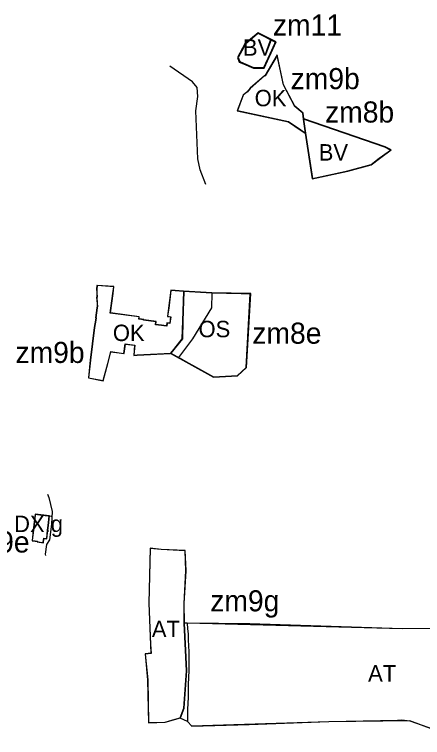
# Model space of a CAD drawing. Extents: x -555070 to -553076, y -1186731 to -1182766.
# Drawn here: x -554417 to -554069, y -1184951 to -1184334 of the extents above; entities that cross this region are included whole.
import ezdxf

# ---------------------------------------------------------------- set-up
doc = ezdxf.new("R2010")
doc.units = 0
for name, color, linetype in [('HRANICE_ZMENY_DO_KOO', 7, 'Continuous'), ('Level 10', 7, 'Continuous'), ('Level 13', 7, 'Continuous'), ('Level 52', 7, 'Continuous'), ('Level 59', 7, 'Continuous'), ('Level 6', 7, 'Continuous'), ('MISTNI_KOMUNIKACE_stav', 7, 'Continuous'), ('OBRYS_PLOCH', 7, 'Continuous'), ('stav_AT', 7, 'Continuous'), ('stav_BV', 7, 'Continuous'), ('stav_DS', 7, 'Continuous'), ('stav_DXg', 7, 'Continuous'), ('stav_OK', 7, 'Continuous'), ('stav_OS', 7, 'Continuous'), ('ZU_plocha_aktualizace', 7, 'Continuous')]:
    doc.layers.add(name, color=color, linetype=linetype)

msp = doc.modelspace()

# ---------------------------------------------------------------- linework, layer by layer
at = {"layer": 'HRANICE_ZMENY_DO_KOO'}
msp.add_line((-554170.7, -1184423.54), (-554169.02, -1184435.57), dxfattribs=at)
for points in [[(-554204.25, -1184380.05), (-554194.19, -1184357.79), (-554209.52, -1184350.02), (-554220.67, -1184359.48), (-554226.98, -1184370.98), (-554225.47, -1184374.96), (-554221.96, -1184376.43), (-554213.49, -1184380), (-554211.97, -1184380.01)], [(-554399.94, -1184765.08), (-554400.17, -1184767.15), (-554400.44, -1184769.55), (-554400.93, -1184774.02), (-554401.95, -1184783.16), (-554399.44, -1184783.43), (-554397.51, -1184783.67), (-554397.57, -1184784.17), (-554392.25, -1184784.89), (-554391.85, -1184781.28), (-554389.33, -1184781.56), (-554388.51, -1184774.24), (-554388.05, -1184770.15), (-554387.22, -1184761.92), (-554399.42, -1184760.41)], [(-554301.44, -1184789.58), (-554302.64, -1184836.28), (-554300.72, -1184879.16), (-554305.71, -1184879.61), (-554303.67, -1184901.89), (-554302.85, -1184938.39), (-554288.7, -1184937.94), (-554275.67, -1184934.24), (-554272.55, -1184925.87), (-554270.19, -1184894.22), (-554272.24, -1184853.44), (-554272.28, -1184836.55), (-554270.85, -1184808.75), (-554271.5, -1184791.46), (-554292.05, -1184790.49)]]:
    msp.add_lwpolyline(points, close=True, dxfattribs=at)
for points in [[(-554170.53, -1184423.3), (-554171.2, -1184418.47), (-554178.03, -1184412.62), (-554187.72, -1184394.38), (-554193.22, -1184368.87), (-554203.65, -1184386.6), (-554203.99, -1184386.56), (-554216.26, -1184397.25), (-554218.76, -1184400.42), (-554219.11, -1184400.51), (-554222.23, -1184403.12), (-554227.38, -1184416.4), (-554183.67, -1184425.84), (-554173.56, -1184432.74), (-554172.15, -1184433.69), (-554169.35, -1184435.59)], [(-554169.32, -1184435.56), (-554169.32, -1184435.61), (-554163.45, -1184474.47), (-554132.96, -1184468.04), (-554113.03, -1184462.64), (-554106.06, -1184457.1), (-554096.22, -1184449.91), (-554101.32, -1184447.27), (-554170.49, -1184423.29)], [(-554273.04, -1184570.31), (-554283.81, -1184569.6), (-554285.81, -1184584.81), (-554286.74, -1184591.94), (-554284.08, -1184592.29), (-554284.75, -1184597.62), (-554287.08, -1184597.32), (-554287.42, -1184599.95), (-554289.84, -1184599.65), (-554291.82, -1184599.4), (-554296.54, -1184598.82), (-554296.2, -1184596.16), (-554306.74, -1184594.81), (-554306.7, -1184594.51), (-554308.7, -1184594.25), (-554310.86, -1184593.98), (-554310.63, -1184592.16), (-554335.2, -1184588.84), (-554332.98, -1184572.3), (-554332.19, -1184566.38), (-554346.75, -1184565.41), (-554346.94, -1184568.7), (-554346.86, -1184571.43), (-554346.75, -1184575.32), (-554347.06, -1184575.34), (-554346.6, -1184580.77), (-554346.54, -1184583.06), (-554346.72, -1184584.4), (-554347.88, -1184593.15), (-554347.58, -1184593.18), (-554347.84, -1184595.11), (-554349.06, -1184601.17), (-554352.43, -1184629.22), (-554354, -1184644.34), (-554341.37, -1184646.71), (-554337.36, -1184632.03), (-554334.77, -1184622.09), (-554327.87, -1184623.02), (-554323.62, -1184623.6), (-554322.51, -1184615.46), (-554314.58, -1184616.47), (-554315.42, -1184625.1), (-554312.31, -1184624.93), (-554284.35, -1184623.41), (-554284.24, -1184623.27)], [(-554284.26, -1184623.26), (-554247.54, -1184643.65), (-554226.85, -1184642.64), (-554219.22, -1184635.44), (-554215.77, -1184572.36), (-554248.91, -1184571.82), (-554273.04, -1184570.31)], [(-554283.34, -1184622.57), (-554273.98, -1184610.94), (-554273.55, -1184595.75), (-554272.83, -1184570.65)], [(-554272.24, -1184853.24), (-554269.87, -1184853.21), (-554086.74, -1184858.06), (-553988.58, -1184857.13), (-553905.89, -1184852.24), (-553902.54, -1184904.97), (-553896.32, -1184936.49), (-553914.33, -1184946.76), (-553944.12, -1184950.99), (-554005.65, -1184950.01), (-554060.25, -1184944.18), (-554080.26, -1184936.83), (-554149.14, -1184937.65), (-554266, -1184941.39), (-554269.56, -1184937.38), (-554275.75, -1184934.43)]]:
    msp.add_lwpolyline(points, dxfattribs=at)
at = {"layer": 'Level 13'}
for p, q in [((-554210.23, -1184351.28), (-554220.28, -1184359.8)), ((-554209.45, -1184350.62), (-554210.23, -1184351.28)), ((-554194.84, -1184358.02), (-554209.45, -1184350.62)), ((-554220.28, -1184359.8), (-554226.43, -1184371.02)), ((-554199.26, -1184367.81), (-554195.27, -1184358.97)), ((-554195.27, -1184358.97), (-554194.84, -1184358.02)), ((-554226.43, -1184371.02), (-554225.08, -1184374.58)), ((-554204.57, -1184379.55), (-554199.26, -1184367.81)), ((-554225.08, -1184374.58), (-554221.77, -1184375.97)), ((-554221.77, -1184375.97), (-554213.39, -1184379.5)), ((-554213.39, -1184379.5), (-554211.97, -1184379.51)), ((-554211.97, -1184379.51), (-554206.78, -1184379.54)), ((-554206.78, -1184379.54), (-554206.13, -1184379.54)), ((-554206.13, -1184379.54), (-554204.57, -1184379.55)), ((-554170.7, -1184423.54), (-554169.02, -1184435.57)), ((-554101.44, -1184447.55), (-554170.7, -1184423.54)), ((-554169.02, -1184435.57), (-554163.2, -1184474.11)), ((-554106.24, -1184456.86), (-554096.79, -1184449.95)), ((-554096.79, -1184449.95), (-554101.44, -1184447.55)), ((-554163.2, -1184474.11), (-554133.03, -1184467.75)), ((-554248.93, -1184572.12), (-554272.74, -1184570.53)), ((-554223.99, -1184572.53), (-554248.93, -1184572.12)), ((-554216.08, -1184572.66), (-554223.99, -1184572.53)), ((-554223.99, -1184572.53), (-554223.99, -1184572.53)), ((-554283.78, -1184623.18), (-554277.24, -1184626.81)), ((-554277.24, -1184626.81), (-554271.13, -1184630.21)), ((-554271.13, -1184630.21), (-554247.47, -1184643.35)), ((-554247.47, -1184643.35), (-554226.98, -1184642.35))]:
    msp.add_line(p, q, dxfattribs=at)
for points in [[(-554133.03, -1184467.75), (-554113.17, -1184462.37), (-554106.24, -1184456.86)], [(-554272.74, -1184570.53), (-554273.46, -1184595.6), (-554273.9, -1184610.9), (-554283.78, -1184623.18)], [(-554226.98, -1184642.35), (-554219.51, -1184635.3), (-554216.08, -1184572.66)], [(-554223.99, -1184572.53), (-554223.99, -1184572.53)]]:
    msp.add_lwpolyline(points, dxfattribs=at)
at = {"layer": 'Level 52'}
for points in [[(-554163.2, -1184474.11), (-554133.03, -1184467.75), (-554113.17, -1184462.37), (-554106.24, -1184456.86), (-554096.79, -1184449.95)], [(-554275.96, -1184627.52), (-554271.13, -1184630.21), (-554247.47, -1184643.35), (-554226.98, -1184642.35), (-554219.51, -1184635.3), (-554216.08, -1184572.66)]]:
    msp.add_lwpolyline(points, dxfattribs=at)
at = {"layer": 'Level 6'}
msp.add_lwpolyline([(-554254.04, -1184479.36), (-554258.7, -1184466.92), (-554260.67, -1184457.41), (-554262.38, -1184416.47), (-554260.91, -1184404.26), (-554261.32, -1184396.65), (-554265.33, -1184391.9), (-554284.73, -1184378.38)], dxfattribs=at)
at = {"layer": 'MISTNI_KOMUNIKACE_stav'}
msp.add_lwpolyline([(-554388.84, -1184743.39), (-554387.7, -1184746.36), (-554384.96, -1184758.32), (-554385.53, -1184769.11), (-554387.14, -1184782.39), (-554389.79, -1184786.41), (-554390.89, -1184794.71), (-554390.5, -1184795.62)], dxfattribs=at)
at = {"layer": 'OBRYS_PLOCH'}
for p, q in [((-554210.23, -1184351.28), (-554220.28, -1184359.8)), ((-554209.45, -1184350.62), (-554210.23, -1184351.28)), ((-554194.84, -1184358.02), (-554209.45, -1184350.62)), ((-554220.28, -1184359.8), (-554226.43, -1184371.02)), ((-554199.26, -1184367.81), (-554195.27, -1184358.97)), ((-554195.27, -1184358.97), (-554194.84, -1184358.02)), ((-554226.43, -1184371.02), (-554225.08, -1184374.58)), ((-554204.57, -1184379.55), (-554199.26, -1184367.81)), ((-554193.31, -1184369.41), (-554203.54, -1184386.81)), ((-554225.08, -1184374.58), (-554221.77, -1184375.97)), ((-554221.77, -1184375.97), (-554213.39, -1184379.5)), ((-554213.39, -1184379.5), (-554211.97, -1184379.51)), ((-554211.97, -1184379.51), (-554206.78, -1184379.54)), ((-554206.78, -1184379.54), (-554206.13, -1184379.54)), ((-554206.13, -1184379.54), (-554204.57, -1184379.55)), ((-554171.39, -1184418.57), (-554178.19, -1184412.75)), ((-554227.11, -1184416.25), (-554183.59, -1184425.65)), ((-554170.7, -1184423.54), (-554171.39, -1184418.57)), ((-554183.59, -1184425.65), (-554173.45, -1184432.57)), ((-554170.7, -1184423.54), (-554169.02, -1184435.57)), ((-554101.44, -1184447.55), (-554170.7, -1184423.54)), ((-554169.02, -1184435.57), (-554170.7, -1184423.54)), ((-554173.45, -1184432.57), (-554172.04, -1184433.52)), ((-554172.04, -1184433.52), (-554169.02, -1184435.57)), ((-554169.02, -1184435.57), (-554163.2, -1184474.11)), ((-554106.24, -1184456.86), (-554096.79, -1184449.95)), ((-554096.79, -1184449.95), (-554101.44, -1184447.55)), ((-554163.2, -1184474.11), (-554133.03, -1184467.75)), ((-554248.93, -1184572.12), (-554272.74, -1184570.53)), ((-554223.99, -1184572.53), (-554248.93, -1184572.12)), ((-554216.08, -1184572.66), (-554223.99, -1184572.53)), ((-554223.99, -1184572.53), (-554223.99, -1184572.53)), ((-554283.78, -1184623.18), (-554247.47, -1184643.35)), ((-554283.78, -1184623.18), (-554277.24, -1184626.81)), ((-554277.24, -1184626.81), (-554271.13, -1184630.21)), ((-554271.13, -1184630.21), (-554247.47, -1184643.35)), ((-554247.47, -1184643.35), (-554226.98, -1184642.35)), ((-554399.24, -1184760.63), (-554399.74, -1184765.1)), ((-554393.26, -1184761.37), (-554399.24, -1184760.63)), ((-554399.74, -1184765.1), (-554399.97, -1184767.17)), ((-554387.44, -1184762.09), (-554393.26, -1184761.37)), ((-554388.25, -1184770.13), (-554387.44, -1184762.09)), ((-554400.24, -1184769.57), (-554400.73, -1184774.04)), ((-554399.97, -1184767.17), (-554400.24, -1184769.57)), ((-554401.23, -1184778.51), (-554401.73, -1184782.98)), ((-554400.73, -1184774.04), (-554401.23, -1184778.51)), ((-554401.73, -1184782.98), (-554399.42, -1184783.23)), ((-554399.42, -1184783.23), (-554397.29, -1184783.5)), ((-554397.29, -1184783.5), (-554397.35, -1184784)), ((-554397.35, -1184784), (-554392.43, -1184784.66)), ((-554392.43, -1184784.66), (-554392.03, -1184781.06)), ((-554392.03, -1184781.06), (-554389.51, -1184781.34)), ((-554301.25, -1184789.8), (-554302.44, -1184836.28)), ((-554292.06, -1184790.69), (-554301.25, -1184789.8)), ((-554271.69, -1184791.65), (-554292.06, -1184790.69)), ((-554271.05, -1184808.75), (-554271.69, -1184791.65)), ((-554302.44, -1184836.28), (-554301.22, -1184871.51)), ((-554270.39, -1184894.22), (-554272.44, -1184853.45)), ((-554216.47, -1184853.91), (-554269.87, -1184853.41)), ((-554269.87, -1184853.41), (-554269.56, -1184858.15)), ((-554086.74, -1184858.26), (-554216.47, -1184853.91)), ((-553988.57, -1184857.33), (-554086.74, -1184858.26)), ((-554301.22, -1184871.51), (-554300.51, -1184879.34)), ((-554300.51, -1184879.34), (-554305.49, -1184879.79)), ((-554305.49, -1184879.79), (-554303.47, -1184901.88)), ((-554303.47, -1184901.88), (-554302.65, -1184938.18)), ((-554302.65, -1184938.18), (-554288.73, -1184937.74)), ((-554288.73, -1184937.74), (-554279.99, -1184935.26))]:
    msp.add_line(p, q, dxfattribs=at)
for points in [[(-554178.19, -1184412.75), (-554187.91, -1184394.45), (-554193.31, -1184369.41)], [(-554203.54, -1184386.81), (-554203.92, -1184386.77), (-554216.11, -1184397.39), (-554218.65, -1184400.6), (-554219.02, -1184400.69), (-554222.06, -1184403.24), (-554227.11, -1184416.25)], [(-554133.03, -1184467.75), (-554113.17, -1184462.37), (-554106.24, -1184456.86)], [(-554272.74, -1184570.53), (-554273.46, -1184595.6), (-554273.9, -1184610.9), (-554283.78, -1184623.18)], [(-554226.98, -1184642.35), (-554219.51, -1184635.3), (-554216.08, -1184572.66)], [(-554223.99, -1184572.53), (-554223.99, -1184572.53)], [(-554389.51, -1184781.34), (-554388.71, -1184774.22), (-554388.25, -1184770.13)], [(-554272.44, -1184853.45), (-554272.48, -1184836.55), (-554271.05, -1184808.75)], [(-554269.56, -1184858.15), (-554269.11, -1184862.54), (-554269.07, -1184863.55), (-554268.92, -1184867.71), (-554268.65, -1184872.8), (-554268.39, -1184877.88), (-554268.44, -1184885.89), (-554268.51, -1184889.87), (-554268.58, -1184893.83), (-554268.93, -1184905.83), (-554269.02, -1184911.25), (-554269.11, -1184916.67), (-554269.51, -1184927.1), (-554269.45, -1184933.6), (-554269.44, -1184937.22)], [(-554279.99, -1184935.26), (-554275.82, -1184934.08), (-554272.75, -1184925.83), (-554270.39, -1184894.22)], [(-554269.44, -1184937.22), (-554265.91, -1184941.19), (-554217.06, -1184939.95), (-554149.14, -1184937.45)], [(-554149.14, -1184937.45), (-554090.76, -1184936.24), (-554087.05, -1184935.87), (-554080.23, -1184936.63), (-554060.2, -1184943.98)]]:
    msp.add_lwpolyline(points, dxfattribs=at)
msp.add_lwpolyline([(-554341.51, -1184646.48), (-554337.55, -1184631.98), (-554334.92, -1184621.87), (-554327.84, -1184622.82), (-554323.79, -1184623.37), (-554322.68, -1184615.23), (-554314.36, -1184616.3), (-554315.2, -1184624.89), (-554312.32, -1184624.73), (-554283.78, -1184623.18), (-554273.9, -1184610.9), (-554273.46, -1184595.6), (-554272.74, -1184570.53), (-554283.64, -1184569.81), (-554285.61, -1184584.84), (-554286.52, -1184591.77), (-554283.86, -1184592.12), (-554284.58, -1184597.84), (-554286.91, -1184597.54), (-554287.25, -1184600.17), (-554289.86, -1184599.85), (-554291.84, -1184599.6), (-554296.76, -1184598.99), (-554296.42, -1184596.33), (-554306.96, -1184594.98), (-554306.92, -1184594.68), (-554308.73, -1184594.45), (-554311.09, -1184594.15), (-554310.85, -1184592.33), (-554335.42, -1184589.01), (-554333.18, -1184572.27), (-554332.42, -1184566.56), (-554346.56, -1184565.62), (-554346.74, -1184568.7), (-554346.66, -1184571.42), (-554346.54, -1184575.51), (-554346.84, -1184575.53), (-554346.4, -1184580.76), (-554346.34, -1184583.07), (-554346.52, -1184584.43), (-554347.65, -1184592.97), (-554347.35, -1184593), (-554347.64, -1184595.14), (-554348.86, -1184601.2), (-554352.23, -1184629.24), (-554353.78, -1184644.18)], close=True, dxfattribs=at)
at = {"layer": 'stav_AT'}
for p, q in [((-554301.25, -1184789.8), (-554302.44, -1184836.28)), ((-554292.06, -1184790.69), (-554301.25, -1184789.8)), ((-554271.69, -1184791.65), (-554292.06, -1184790.69)), ((-554271.05, -1184808.75), (-554271.69, -1184791.65)), ((-554302.44, -1184836.28), (-554301.22, -1184871.51)), ((-554270.39, -1184894.22), (-554272.44, -1184853.45)), ((-554216.47, -1184853.91), (-554269.87, -1184853.41)), ((-554269.87, -1184853.41), (-554269.56, -1184858.15)), ((-554086.74, -1184858.26), (-554216.47, -1184853.91)), ((-553988.57, -1184857.33), (-554086.74, -1184858.26)), ((-554301.22, -1184871.51), (-554300.51, -1184879.34)), ((-554300.51, -1184879.34), (-554305.49, -1184879.79)), ((-554305.49, -1184879.79), (-554303.47, -1184901.88)), ((-554303.47, -1184901.88), (-554302.65, -1184938.18)), ((-554302.65, -1184938.18), (-554288.73, -1184937.74)), ((-554288.73, -1184937.74), (-554279.99, -1184935.26))]:
    msp.add_line(p, q, dxfattribs=at)
for points in [[(-554272.44, -1184853.45), (-554272.48, -1184836.55), (-554271.05, -1184808.75)], [(-554269.56, -1184858.15), (-554269.11, -1184862.54), (-554269.07, -1184863.55), (-554268.92, -1184867.71), (-554268.65, -1184872.8), (-554268.39, -1184877.88), (-554268.44, -1184885.89), (-554268.51, -1184889.87), (-554268.58, -1184893.83), (-554268.93, -1184905.83), (-554269.02, -1184911.25), (-554269.11, -1184916.67), (-554269.51, -1184927.1), (-554269.45, -1184933.6), (-554269.44, -1184937.22)], [(-554279.99, -1184935.26), (-554275.82, -1184934.08), (-554272.75, -1184925.83), (-554270.39, -1184894.22)], [(-554269.44, -1184937.22), (-554265.91, -1184941.19), (-554217.06, -1184939.95), (-554149.14, -1184937.45)], [(-554149.14, -1184937.45), (-554090.76, -1184936.24), (-554087.05, -1184935.87), (-554080.23, -1184936.63), (-554060.2, -1184943.98)]]:
    msp.add_lwpolyline(points, dxfattribs=at)
at = {"layer": 'stav_BV'}
for p, q in [((-554210.23, -1184351.28), (-554220.28, -1184359.8)), ((-554209.45, -1184350.62), (-554210.23, -1184351.28)), ((-554194.84, -1184358.02), (-554209.45, -1184350.62)), ((-554220.28, -1184359.8), (-554226.43, -1184371.02)), ((-554199.26, -1184367.81), (-554195.27, -1184358.97)), ((-554195.27, -1184358.97), (-554194.84, -1184358.02)), ((-554226.43, -1184371.02), (-554225.08, -1184374.58)), ((-554204.57, -1184379.55), (-554199.26, -1184367.81)), ((-554225.08, -1184374.58), (-554221.77, -1184375.97)), ((-554221.77, -1184375.97), (-554213.39, -1184379.5)), ((-554213.39, -1184379.5), (-554211.97, -1184379.51)), ((-554211.97, -1184379.51), (-554206.78, -1184379.54)), ((-554206.78, -1184379.54), (-554206.13, -1184379.54)), ((-554206.13, -1184379.54), (-554204.57, -1184379.55)), ((-554170.7, -1184423.54), (-554169.02, -1184435.57)), ((-554101.44, -1184447.55), (-554170.7, -1184423.54)), ((-554169.02, -1184435.57), (-554163.2, -1184474.11)), ((-554106.24, -1184456.86), (-554096.79, -1184449.95)), ((-554096.79, -1184449.95), (-554101.44, -1184447.55)), ((-554163.2, -1184474.11), (-554133.03, -1184467.75))]:
    msp.add_line(p, q, dxfattribs=at)
msp.add_lwpolyline([(-554133.03, -1184467.75), (-554113.17, -1184462.37), (-554106.24, -1184456.86)], dxfattribs=at)
at = {"layer": 'stav_DS'}
msp.add_lwpolyline([(-554399.24, -1184760.63), (-554393.26, -1184761.37), (-554385.76, -1184762.3)], dxfattribs=at)
at = {"layer": 'stav_DXg'}
for p, q in [((-554399.24, -1184760.63), (-554399.74, -1184765.1)), ((-554393.26, -1184761.37), (-554399.24, -1184760.63)), ((-554399.74, -1184765.1), (-554399.97, -1184767.17)), ((-554387.44, -1184762.09), (-554393.26, -1184761.37)), ((-554388.25, -1184770.13), (-554387.44, -1184762.09)), ((-554400.24, -1184769.57), (-554400.73, -1184774.04)), ((-554399.97, -1184767.17), (-554400.24, -1184769.57)), ((-554401.23, -1184778.51), (-554401.73, -1184782.98)), ((-554400.73, -1184774.04), (-554401.23, -1184778.51)), ((-554401.73, -1184782.98), (-554399.42, -1184783.23)), ((-554399.42, -1184783.23), (-554397.29, -1184783.5)), ((-554397.29, -1184783.5), (-554397.35, -1184784)), ((-554397.35, -1184784), (-554392.43, -1184784.66)), ((-554392.43, -1184784.66), (-554392.03, -1184781.06)), ((-554392.03, -1184781.06), (-554389.51, -1184781.34))]:
    msp.add_line(p, q, dxfattribs=at)
msp.add_lwpolyline([(-554389.51, -1184781.34), (-554388.71, -1184774.22), (-554388.25, -1184770.13)], dxfattribs=at)
at = {"layer": 'stav_OK'}
for p, q in [((-554193.31, -1184369.41), (-554203.54, -1184386.81)), ((-554171.39, -1184418.57), (-554178.19, -1184412.75)), ((-554227.11, -1184416.25), (-554183.59, -1184425.65)), ((-554170.7, -1184423.54), (-554171.39, -1184418.57)), ((-554183.59, -1184425.65), (-554173.45, -1184432.57)), ((-554169.02, -1184435.57), (-554170.7, -1184423.54)), ((-554173.45, -1184432.57), (-554172.04, -1184433.52)), ((-554172.04, -1184433.52), (-554169.02, -1184435.57))]:
    msp.add_line(p, q, dxfattribs=at)
for points in [[(-554178.19, -1184412.75), (-554187.91, -1184394.45), (-554193.31, -1184369.41)], [(-554203.54, -1184386.81), (-554203.92, -1184386.77), (-554216.11, -1184397.39), (-554218.65, -1184400.6), (-554219.02, -1184400.69), (-554222.06, -1184403.24), (-554227.11, -1184416.25)]]:
    msp.add_lwpolyline(points, dxfattribs=at)
msp.add_lwpolyline([(-554341.51, -1184646.48), (-554337.55, -1184631.98), (-554334.92, -1184621.87), (-554327.84, -1184622.82), (-554323.79, -1184623.37), (-554322.68, -1184615.23), (-554314.36, -1184616.3), (-554315.2, -1184624.89), (-554312.32, -1184624.73), (-554283.78, -1184623.18), (-554273.9, -1184610.9), (-554273.46, -1184595.6), (-554272.74, -1184570.53), (-554283.64, -1184569.81), (-554285.61, -1184584.84), (-554286.52, -1184591.77), (-554283.86, -1184592.12), (-554284.58, -1184597.84), (-554286.91, -1184597.54), (-554287.25, -1184600.17), (-554289.86, -1184599.85), (-554291.84, -1184599.6), (-554296.76, -1184598.99), (-554296.42, -1184596.33), (-554306.96, -1184594.98), (-554306.92, -1184594.68), (-554308.73, -1184594.45), (-554311.09, -1184594.15), (-554310.85, -1184592.33), (-554335.42, -1184589.01), (-554333.18, -1184572.27), (-554332.42, -1184566.56), (-554346.56, -1184565.62), (-554346.74, -1184568.7), (-554346.66, -1184571.42), (-554346.54, -1184575.51), (-554346.84, -1184575.53), (-554346.4, -1184580.76), (-554346.34, -1184583.07), (-554346.52, -1184584.43), (-554347.65, -1184592.97), (-554347.35, -1184593), (-554347.64, -1184595.14), (-554348.86, -1184601.2), (-554352.23, -1184629.24), (-554353.78, -1184644.18)], close=True, dxfattribs=at)
at = {"layer": 'stav_OS'}
for p, q in [((-554248.93, -1184572.12), (-554272.74, -1184570.53)), ((-554223.99, -1184572.53), (-554248.93, -1184572.12)), ((-554216.08, -1184572.66), (-554223.99, -1184572.53)), ((-554223.99, -1184572.53), (-554223.99, -1184572.53)), ((-554283.78, -1184623.18), (-554247.47, -1184643.35)), ((-554283.78, -1184623.18), (-554277.24, -1184626.81)), ((-554277.24, -1184626.81), (-554271.13, -1184630.21)), ((-554271.13, -1184630.21), (-554247.47, -1184643.35)), ((-554247.47, -1184643.35), (-554226.98, -1184642.35))]:
    msp.add_line(p, q, dxfattribs=at)
for points in [[(-554272.74, -1184570.53), (-554273.46, -1184595.6), (-554273.9, -1184610.9), (-554283.78, -1184623.18)], [(-554226.98, -1184642.35), (-554219.51, -1184635.3), (-554216.08, -1184572.66)], [(-554223.99, -1184572.53), (-554223.99, -1184572.53)]]:
    msp.add_lwpolyline(points, dxfattribs=at)
at = {"layer": 'ZU_plocha_aktualizace'}
for p, q in [((-554170.7, -1184423.54), (-554169.02, -1184435.57)), ((-554101.44, -1184447.55), (-554170.7, -1184423.54)), ((-554169.02, -1184435.57), (-554163.2, -1184474.11)), ((-554106.24, -1184456.86), (-554096.79, -1184449.95)), ((-554096.79, -1184449.95), (-554101.44, -1184447.55)), ((-554113.17, -1184462.37), (-554106.24, -1184456.86)), ((-554133.03, -1184467.75), (-554113.17, -1184462.37)), ((-554163.2, -1184474.11), (-554133.03, -1184467.75)), ((-554248.93, -1184572.12), (-554249.13, -1184584.47)), ((-554223.99, -1184572.53), (-554248.93, -1184572.12)), ((-554216.08, -1184572.66), (-554223.99, -1184572.53)), ((-554277.24, -1184626.81), (-554271.13, -1184630.21)), ((-554271.13, -1184630.21), (-554247.47, -1184643.35)), ((-554226.98, -1184642.35), (-554219.51, -1184635.3)), ((-554247.47, -1184643.35), (-554226.98, -1184642.35))]:
    msp.add_line(p, q, dxfattribs=at)
for points in [[(-554219.51, -1184635.3), (-554218.51, -1184616.99), (-554216.08, -1184572.66)], [(-554249.13, -1184584.47), (-554265.44, -1184610.89), (-554277.24, -1184626.81)]]:
    msp.add_lwpolyline(points, dxfattribs=at)

# ---------------------------------------------------------------- texts
at = {"layer": 'Level 10'}
for s, p in [('zm11', (-554196.83, -1184352.34)), ('zm9b', (-554181.71, -1184398.05)), ('zm8b', (-554152.4, -1184426.52)), ('zm8e', (-554214.34, -1184615.12)), ('zm9b', (-554416.06, -1184631.55)), ('zm9e', (-554462.93, -1184793.23)), ('zm9g', (-554250.18, -1184843.39))]:
    msp.add_text(s, height=18, dxfattribs=at).set_placement(p)
at = {"layer": 'Level 59'}
for s, p in [('BV', (-554222.35, -1184369.5)), ('OK', (-554212.37, -1184412.63)), ('BV', (-554157.82, -1184458.95)), ('OK', (-554333.12, -1184612.88)), ('OS', (-554260.19, -1184609.61)), ('DX.g', (-554417.26, -1184775.76)), ('AT', (-554299.94, -1184865.36)), ('AT', (-554115.75, -1184903.2))]:
    msp.add_text(s, height=14, dxfattribs=at).set_placement(p)

doc.saveas('drawing.dxf')
